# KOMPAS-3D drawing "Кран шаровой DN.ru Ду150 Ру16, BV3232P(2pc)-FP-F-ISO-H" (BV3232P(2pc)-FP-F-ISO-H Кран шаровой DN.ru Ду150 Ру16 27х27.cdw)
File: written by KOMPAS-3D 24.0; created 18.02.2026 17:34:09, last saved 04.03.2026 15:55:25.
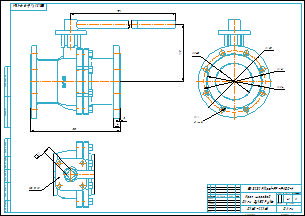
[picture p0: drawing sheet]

Document properties: Автор: R2D2; Форматы листов документа: A2; Полное имя файла: BV3232P(2pc)-FP-F-ISO-H Кран шаровой DN.ru Ду150 Ру16 27х27.m3d; Масса: 41; Наименование: Кран шаровой DN.ru Ду150 Ру16; Количество листов документа: 1; Примечание: D160-22161

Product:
- Part/product: Кран шаровой DN.ru Ду150 Ру16  | designation BV3232P(2pc)-FP-F-ISO-H
    Масса: 41
    Раздел спецификации: Прочие изделия
    Примечание: D160-22161

Views: Проекционный вид 2, Проекционный вид 3
Referenced files in E:\Работа\Зайцев\BV3232P(2pc)-FP-F-ISO-H Кран шаровой DN.ru Ду15-300 Ру16-40\DN150 PN16 27х27\: BV3232P(2pc)-FP-F-ISO-H Кран шаровой DN.ru Ду150 Ру16 27х27.m3d
Referenced files in E:\Работа\Зайцев\Для компаса\: чертеж DN.ru А3.cdt
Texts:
  BV3232P(2pc)-FP-F-ISO-H
  ISO 5211
  чертеж DN.ru А3.cdt
  Кран шаровой
  DN.ru Ду150 Ру16
  Кран шаровой DN.ru Ду150 Ру16
  BV3232P(2pc)-FP-F-ISO-H Кран шаровой DN.ru Ду150 Ру16
Dimensions and other numbers on the sheet: 0; 3; 4; 285; 240; 214; 146; 22; 8 отв.; 27; 1:2; 1; 2; 41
